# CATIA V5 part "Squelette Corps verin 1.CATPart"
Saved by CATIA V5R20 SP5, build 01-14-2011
Part number: Squelette Corps verin 1
Bounding box of the stored display mesh (mm): x -145.521 to 0, y -150 to -113.62, z -70 to -10
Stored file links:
  U:\CFAO\Thinkmotion\Squelette Corps verin 1.CATPart
  U:\CFAO\Thinkmotion\Bras Articule.CATProduct
  U:\CFAO\Thinkmotion\Squelette general.CATPart
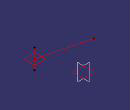
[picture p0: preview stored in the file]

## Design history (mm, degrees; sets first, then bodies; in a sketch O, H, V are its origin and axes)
Set1
  Line1: type PtPt, FirstPoint Point1, SecondPoint Point2
  Line2: type Normal, RefPoint Point1, RefSkin Plane2, Start -30, End 30
  Plane1: type OffsetPt, RefPlane xy-plane, RefPoint Point1
Set2
  Point1: linked copy from another document
  Point2: linked copy from another document
  Plane2: linked copy from another document
Body1 (main body)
